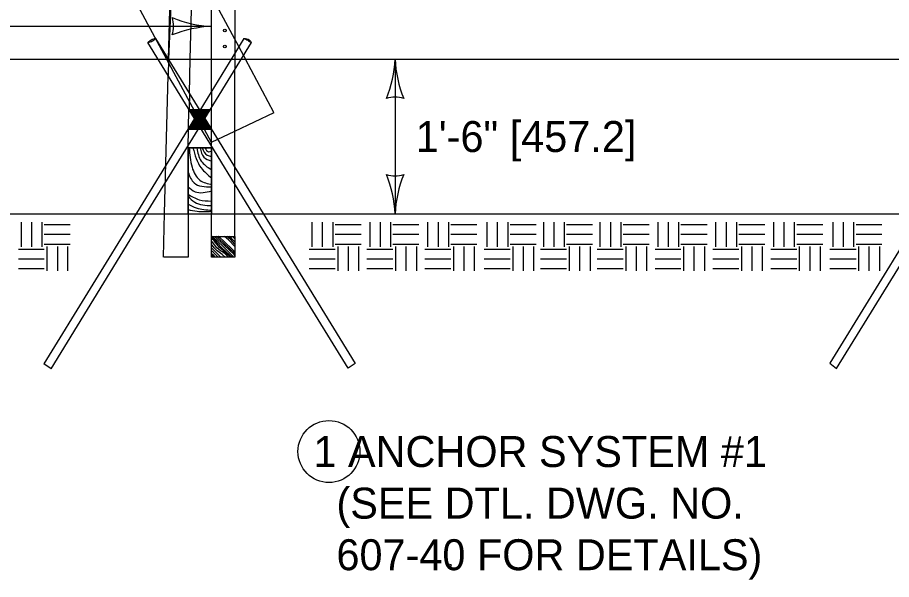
# Model space of a CAD drawing. Extents: x 49991.4 to 50021, y 49987.6 to 50011.4.
# Drawn here: x 50002.489 to 50004.182, y 49993.662 to 49994.752 of the extents above; entities that cross this region are included whole.
import ezdxf

# ---------------------------------------------------------------- set-up
doc = ezdxf.new("R2010")
doc.units = 0
for name, color, linetype in [('Level 1', 7, 'Continuous'), ('Level 2', 7, 'Continuous'), ('Level 3', 7, 'Continuous'), ('Level 4', 7, 'Continuous')]:
    doc.layers.add(name, color=color, linetype=linetype)

msp = doc.modelspace()

# ---------------------------------------------------------------- linework, layer by layer
at = {"layer": 'Level 1'}
for p, q in [((50002.7564, 49994.7111), (50002.842, 49994.5716)), ((50002.9277, 49994.7111), (50002.842, 49994.5716)), ((50002.8321, 49994.5557), (50002.7415, 49994.7031)), ((50002.8518, 49994.5557), (50002.9424, 49994.7031)), ((50000.6947, 49994.6706), (50004.302, 49994.6706)), ((50002.8221, 49994.604), (50002.8238, 49994.6706)), ((50002.865, 49994.6091), (50002.865, 49994.6706)), ((50002.9859, 49994.5674), (50002.9306, 49994.6706)), ((50002.7738, 49994.3725), (50002.7808, 49994.6392)), ((50002.9103, 49994.3725), (50002.9103, 49994.651)), ((50002.8194, 49994.499), (50002.8212, 49994.5733)), ((50002.8214, 49994.5732), (50002.8626, 49994.5732)), ((50002.8226, 49994.5711), (50002.8613, 49994.5711)), ((50002.865, 49994.3725), (50002.865, 49994.5772)), ((50002.8321, 49994.5557), (50002.7194, 49994.3721)), ((50002.824, 49994.5689), (50002.86, 49994.5689)), ((50002.8252, 49994.5668), (50002.8587, 49994.5668)), ((50002.8266, 49994.5648), (50002.8574, 49994.5648)), ((50002.8278, 49994.5626), (50002.8561, 49994.5626)), ((50002.8292, 49994.5605), (50002.8548, 49994.5605)), ((50002.8304, 49994.5584), (50002.8535, 49994.5584)), ((50002.8312, 49994.5541), (50002.8528, 49994.5541)), ((50002.8318, 49994.5562), (50002.8522, 49994.5562)), ((50002.8518, 49994.5558), (50002.9649, 49994.3716)), ((50002.9103, 49994.5314), (50002.9862, 49994.5674)), ((50002.7391, 49994.3721), (50002.842, 49994.5397)), ((50002.8207, 49994.5371), (50002.8632, 49994.5371)), ((50002.8221, 49994.5392), (50002.8619, 49994.5392)), ((50002.8233, 49994.5412), (50002.8606, 49994.5412)), ((50002.8246, 49994.5434), (50002.8592, 49994.5434)), ((50002.826, 49994.5455), (50002.858, 49994.5455)), ((50002.8273, 49994.5477), (50002.8567, 49994.5477)), ((50002.8286, 49994.5498), (50002.8553, 49994.5498)), ((50002.8299, 49994.5519), (50002.854, 49994.5519)), ((50002.9452, 49994.3716), (50002.842, 49994.5397)), ((50002.8194, 49994.5349), (50002.8645, 49994.5349)), ((50002.8646, 49994.499), (50002.8194, 49994.499)), ((50002.8194, 49994.499), (50002.8194, 49994.3713)), ((50002.8194, 49994.499), (50002.8646, 49994.499)), ((50002.8194, 49994.3713), (50002.8194, 49994.499)), ((50002.8646, 49994.3713), (50002.8646, 49994.499)), ((50002.8646, 49994.499), (50002.8646, 49994.3713)), ((50002.865, 49994.3725), (50002.865, 49994.4363)), ((49999.8901, 49994.3711), (50006.2392, 49994.3711)), ((50002.8194, 49994.3713), (50002.8646, 49994.3713)), ((50002.8194, 49994.3713), (50002.8646, 49994.3713)), ((50002.4961, 49994.3547), (50002.4961, 49994.3074)), ((50002.5162, 49994.3547), (50002.5162, 49994.3074)), ((50002.5364, 49994.3547), (50002.5364, 49994.3074)), ((50002.5411, 49994.3503), (50002.5914, 49994.3503)), ((50003.0592, 49994.3547), (50003.0592, 49994.3074)), ((50003.0794, 49994.3547), (50003.0794, 49994.3074)), ((50003.0996, 49994.3547), (50003.0996, 49994.3074)), ((50003.1042, 49994.3503), (50003.1545, 49994.3503)), ((50003.1714, 49994.3547), (50003.1714, 49994.3074)), ((50003.1916, 49994.3547), (50003.1916, 49994.3074)), ((50003.2116, 49994.3547), (50003.2116, 49994.3074)), ((50003.2163, 49994.3503), (50003.2667, 49994.3503)), ((50003.2835, 49994.3547), (50003.2835, 49994.3074)), ((50003.3036, 49994.3547), (50003.3036, 49994.3074)), ((50003.3238, 49994.3547), (50003.3238, 49994.3074)), ((50003.3285, 49994.3503), (50003.3788, 49994.3503)), ((50003.3983, 49994.3547), (50003.3983, 49994.3074)), ((50003.4184, 49994.3547), (50003.4184, 49994.3074)), ((50003.4386, 49994.3547), (50003.4386, 49994.3074)), ((50003.4433, 49994.3503), (50003.4936, 49994.3503)), ((50003.5078, 49994.3547), (50003.5078, 49994.3074)), ((50003.5278, 49994.3547), (50003.5278, 49994.3074)), ((50003.5479, 49994.3547), (50003.5479, 49994.3074)), ((50003.5526, 49994.3503), (50003.603, 49994.3503)), ((50003.6172, 49994.3547), (50003.6172, 49994.3074)), ((50003.6374, 49994.3547), (50003.6374, 49994.3074)), ((50003.6574, 49994.3547), (50003.6574, 49994.3074)), ((50003.6622, 49994.3503), (50003.7125, 49994.3503)), ((50003.7293, 49994.3547), (50003.7293, 49994.3074)), ((50003.7494, 49994.3547), (50003.7494, 49994.3074)), ((50003.7696, 49994.3547), (50003.7696, 49994.3074)), ((50003.7742, 49994.3503), (50003.8246, 49994.3503)), ((50003.8413, 49994.3547), (50003.8413, 49994.3074)), ((50003.8615, 49994.3547), (50003.8615, 49994.3074)), ((50003.8816, 49994.3547), (50003.8816, 49994.3074)), ((50003.8863, 49994.3503), (50003.9366, 49994.3503)), ((50003.9535, 49994.3547), (50003.9535, 49994.3074)), ((50003.9735, 49994.3547), (50003.9735, 49994.3074)), ((50003.9937, 49994.3547), (50003.9937, 49994.3074)), ((50003.9984, 49994.3503), (50004.0488, 49994.3503)), ((50004.0682, 49994.3547), (50004.0682, 49994.3074)), ((50004.0883, 49994.3547), (50004.0883, 49994.3074)), ((50004.1085, 49994.3547), (50004.1085, 49994.3074)), ((50004.1132, 49994.3503), (50004.1635, 49994.3503)), ((50002.5411, 49994.3314), (50002.5914, 49994.3314)), ((50003.1042, 49994.3314), (50003.1545, 49994.3314)), ((50003.2163, 49994.3314), (50003.2667, 49994.3314)), ((50003.3285, 49994.3314), (50003.3788, 49994.3314)), ((50003.4433, 49994.3314), (50003.4936, 49994.3314)), ((50003.5526, 49994.3314), (50003.603, 49994.3314)), ((50003.6622, 49994.3314), (50003.7125, 49994.3314)), ((50003.7742, 49994.3314), (50003.8246, 49994.3314)), ((50003.8863, 49994.3314), (50003.9366, 49994.3314)), ((50003.9984, 49994.3314), (50004.0488, 49994.3314)), ((50004.1132, 49994.3314), (50004.1635, 49994.3314)), ((50002.4908, 49994.3029), (50002.5411, 49994.3029)), ((50002.5411, 49994.3124), (50002.5914, 49994.3124)), ((50002.5461, 49994.3078), (50002.5461, 49994.2604)), ((50002.5663, 49994.3078), (50002.5663, 49994.2604)), ((50002.5863, 49994.3078), (50002.5863, 49994.2604)), ((50003.0539, 49994.3029), (50003.1042, 49994.3029)), ((50003.1042, 49994.3124), (50003.1545, 49994.3124)), ((50003.1093, 49994.3078), (50003.1093, 49994.2604)), ((50003.1294, 49994.3078), (50003.1294, 49994.2604)), ((50003.1496, 49994.3078), (50003.1496, 49994.2604)), ((50003.166, 49994.3029), (50003.2163, 49994.3029)), ((50003.2163, 49994.3124), (50003.2667, 49994.3124)), ((50003.2214, 49994.3078), (50003.2214, 49994.2604)), ((50003.2415, 49994.3078), (50003.2415, 49994.2604)), ((50003.2617, 49994.3078), (50003.2617, 49994.2604)), ((50003.2782, 49994.3029), (50003.3285, 49994.3029)), ((50003.3285, 49994.3124), (50003.3788, 49994.3124)), ((50003.3336, 49994.3078), (50003.3336, 49994.2604)), ((50003.3536, 49994.3078), (50003.3536, 49994.2604)), ((50003.3737, 49994.3078), (50003.3737, 49994.2604)), ((50003.393, 49994.3029), (50003.4433, 49994.3029)), ((50003.4433, 49994.3124), (50003.4936, 49994.3124)), ((50003.4483, 49994.3078), (50003.4483, 49994.2604)), ((50003.4684, 49994.3078), (50003.4684, 49994.2604)), ((50003.4885, 49994.3078), (50003.4885, 49994.2604)), ((50003.5023, 49994.3029), (50003.5526, 49994.3029)), ((50003.5526, 49994.3124), (50003.603, 49994.3124)), ((50003.5577, 49994.3078), (50003.5577, 49994.2604)), ((50003.5778, 49994.3078), (50003.5778, 49994.2604)), ((50003.598, 49994.3078), (50003.598, 49994.2604)), ((50003.6118, 49994.3029), (50003.6622, 49994.3029)), ((50003.6622, 49994.3124), (50003.7125, 49994.3124)), ((50003.6671, 49994.3078), (50003.6671, 49994.2604)), ((50003.6873, 49994.3078), (50003.6873, 49994.2604)), ((50003.7074, 49994.3078), (50003.7074, 49994.2604)), ((50003.7239, 49994.3029), (50003.7742, 49994.3029)), ((50003.7742, 49994.3124), (50003.8246, 49994.3124)), ((50003.7793, 49994.3078), (50003.7793, 49994.2604)), ((50003.7993, 49994.3078), (50003.7993, 49994.2604)), ((50003.8195, 49994.3078), (50003.8195, 49994.2604)), ((50003.836, 49994.3029), (50003.8863, 49994.3029)), ((50003.8863, 49994.3124), (50003.9366, 49994.3124)), ((50003.8914, 49994.3078), (50003.8914, 49994.2604)), ((50003.9115, 49994.3078), (50003.9115, 49994.2604)), ((50003.9317, 49994.3078), (50003.9317, 49994.2604)), ((50003.9481, 49994.3029), (50003.9984, 49994.3029)), ((50003.9984, 49994.3124), (50004.0488, 49994.3124)), ((50004.0034, 49994.3078), (50004.0034, 49994.2604)), ((50004.0236, 49994.3078), (50004.0236, 49994.2604)), ((50004.0437, 49994.3078), (50004.0437, 49994.2604)), ((50004.0628, 49994.3029), (50004.1132, 49994.3029)), ((50004.1132, 49994.3124), (50004.1635, 49994.3124)), ((50004.1182, 49994.3078), (50004.1182, 49994.2604)), ((50004.1382, 49994.3078), (50004.1382, 49994.2604)), ((50004.1584, 49994.3078), (50004.1584, 49994.2604)), ((50002.4908, 49994.2841), (50002.5411, 49994.2841)), ((50003.0539, 49994.2841), (50003.1042, 49994.2841)), ((50003.166, 49994.2841), (50003.2163, 49994.2841)), ((50003.2782, 49994.2841), (50003.3285, 49994.2841)), ((50003.393, 49994.2841), (50003.4433, 49994.2841)), ((50003.5023, 49994.2841), (50003.5526, 49994.2841)), ((50003.6118, 49994.2841), (50003.6622, 49994.2841)), ((50003.7239, 49994.2841), (50003.7742, 49994.2841)), ((50003.836, 49994.2841), (50003.8863, 49994.2841)), ((50003.9481, 49994.2841), (50003.9984, 49994.2841)), ((50004.0628, 49994.2841), (50004.1132, 49994.2841)), ((50002.4908, 49994.2651), (50002.5411, 49994.2651)), ((50003.0539, 49994.2651), (50003.1042, 49994.2651)), ((50003.166, 49994.2651), (50003.2163, 49994.2651)), ((50003.2782, 49994.2651), (50003.3285, 49994.2651)), ((50003.393, 49994.2651), (50003.4433, 49994.2651)), ((50003.5023, 49994.2651), (50003.5526, 49994.2651)), ((50003.6118, 49994.2651), (50003.6622, 49994.2651)), ((50003.7239, 49994.2651), (50003.7742, 49994.2651)), ((50003.836, 49994.2651), (50003.8863, 49994.2651)), ((50003.9481, 49994.2651), (50003.9984, 49994.2651)), ((50004.0628, 49994.2651), (50004.1132, 49994.2651))]:
    msp.add_line(p, q, dxfattribs=at)
for centre in [(50002.8907, 49994.7262), (50002.8907, 49994.6955)]:
    msp.add_ellipse(centre, major_axis=(0.00285, 0), ratio=0.940299, dxfattribs=at)
for points in [[(50002.7415, 49994.7031), (50002.7505, 49994.7062), (50002.7564, 49994.7111)], [(50002.7415, 49994.7031), (50002.75, 49994.7093), (50002.7564, 49994.7111)], [(50002.9277, 49994.7111), (50002.9378, 49994.7084), (50002.9424, 49994.7031)], [(50002.9277, 49994.7111), (50002.935, 49994.7074), (50002.9424, 49994.7031)], [(50002.8219, 49994.499), (50002.8272, 49994.4613), (50002.8424, 49994.4364), (50002.8659, 49994.4277)], [(50002.829, 49994.499), (50002.8448, 49994.4601), (50002.8653, 49994.4404)], [(50002.8363, 49994.4988), (50002.8448, 49994.4734), (50002.8642, 49994.4569)], [(50002.8431, 49994.4987), (50002.8501, 49994.481), (50002.8648, 49994.4734)], [(50002.8466, 49994.4988), (50002.8566, 49994.4849), (50002.8642, 49994.4822)], [(50002.8522, 49994.499), (50002.8589, 49994.4914), (50002.8642, 49994.4926)], [(50002.8195, 49994.4519), (50002.8312, 49994.431), (50002.8648, 49994.4233)], [(50002.8195, 49994.4233), (50002.833, 49994.414), (50002.8653, 49994.4155)], [(50002.8189, 49994.4095), (50002.8407, 49994.3985), (50002.8648, 49994.3958)], [(50002.8195, 49994.4051), (50002.8324, 49994.3936), (50002.8653, 49994.387)], [(50002.8195, 49994.3896), (50002.8354, 49994.3826), (50002.8653, 49994.3782)], [(50002.8195, 49994.3792), (50002.8371, 49994.376), (50002.8642, 49994.376)]]:
    msp.add_spline(points, degree=3, dxfattribs=at)
at = {"layer": 'Level 2'}
msp.add_circle((50003.0924, 49993.9104), 0.06, dxfattribs=at)
msp.add_ellipse((50003.326, 49993.6896), major_axis=(0.00285, 0), ratio=0.940299, dxfattribs=at)
at = {"layer": 'Level 3'}
for p, q in [((50002.2108, 49994.7345), (50002.865, 49994.7345)), ((50003.2204, 49994.6707), (50003.2204, 49994.3711))]:
    msp.add_line(p, q, dxfattribs=at)
for centre, radius, start, end in [((50002.8742, 49994.9566), 0.2223, 247.456, 267.6395), ((50002.7368, 49994.7345), 0.0548, 342.1388, 17.8612), ((50002.8765, 49994.5018), 0.233, 92.8273, 112.0772), ((50002.9983, 49994.6798), 0.2223, 337.456, 357.6395), ((50003.4531, 49994.6822), 0.233, 182.8273, 202.0772), ((50003.2204, 49994.5425), 0.0548, 72.1388, 107.8612), ((50003.2204, 49994.4993), 0.0548, 252.1388, 287.8612), ((50002.9877, 49994.3596), 0.233, 2.8273, 22.0772), ((50003.4426, 49994.3619), 0.2223, 157.456, 177.6395)]:
    msp.add_arc(centre, radius, start, end, dxfattribs=at)
at = {"layer": 'Level 4'}
for p, q in [((50002.7241, 49995.054), (50002.9306, 49994.6706)), ((50002.8238, 49994.6706), (50002.8294, 49994.8804)), ((50002.865, 49994.6706), (50002.865, 49994.8246)), ((50002.8648, 49994.5096), (50002.7094, 49994.7984)), ((50002.7872, 49994.7984), (50002.7817, 49994.6706)), ((50002.7817, 49994.6706), (50002.7851, 49994.7984)), ((50002.9103, 49994.7984), (50002.9103, 49994.651)), ((50002.7817, 49994.6706), (50002.7808, 49994.6392)), ((50002.865, 49994.6091), (50002.865, 49994.5772)), ((50002.8221, 49994.604), (50002.8214, 49994.5732)), ((50002.865, 49994.5098), (50002.9103, 49994.5314)), ((50002.7194, 49994.3721), (50002.5401, 49994.0801)), ((50002.5541, 49994.0708), (50002.7391, 49994.3721)), ((50002.7716, 49994.2873), (50002.7738, 49994.3725)), ((50002.8197, 49994.3713), (50002.8197, 49994.2873)), ((50002.865, 49994.2873), (50002.865, 49994.3725)), ((50002.9103, 49994.3272), (50002.9103, 49994.3725)), ((50003.1293, 49994.0717), (50002.9452, 49994.3716)), ((50002.9649, 49994.3716), (50003.1432, 49994.0808)), ((50004.2402, 49994.3712), (50004.0624, 49994.0816)), ((50004.0757, 49994.0715), (50004.2598, 49994.3712)), ((50002.8197, 49994.2873), (50002.7723, 49994.2873)), ((50002.5541, 49994.0708), (50002.5401, 49994.0801)), ((50003.1432, 49994.0808), (50003.1293, 49994.0717)), ((50004.0624, 49994.0816), (50004.0757, 49994.0715))]:
    msp.add_line(p, q, dxfattribs=at)
for points in [[(50002.865, 49994.3272), (50002.9103, 49994.3272), (50002.9103, 49994.2873)], [(50002.9047, 49994.2873), (50002.8939, 49994.297), (50002.8838, 49994.3067), (50002.8711, 49994.32), (50002.865, 49994.3253)], [(50002.902, 49994.2873), (50002.8926, 49994.2958), (50002.8802, 49994.3059), (50002.8698, 49994.3188), (50002.865, 49994.323)], [(50002.8977, 49994.2873), (50002.8912, 49994.2936), (50002.886, 49994.2972), (50002.8821, 49994.2993), (50002.8754, 49994.3055), (50002.8671, 49994.3162), (50002.865, 49994.318)], [(50002.9081, 49994.2873), (50002.9039, 49994.2914), (50002.8897, 49994.3058), (50002.8761, 49994.3187), (50002.8685, 49994.3249), (50002.8657, 49994.3272)], [(50002.9103, 49994.2905), (50002.9086, 49994.292), (50002.8901, 49994.3097), (50002.8708, 49994.3272)], [(50002.9103, 49994.294), (50002.8793, 49994.3235), (50002.8748, 49994.3272)], [(50002.9103, 49994.2974), (50002.9034, 49994.3037), (50002.8912, 49994.3157), (50002.8788, 49994.3271), (50002.8786, 49994.3272)], [(50002.9103, 49994.3075), (50002.8975, 49994.321), (50002.8899, 49994.3272)], [(50002.9103, 49994.3118), (50002.9094, 49994.3127), (50002.9022, 49994.3211), (50002.8945, 49994.3272)], [(50002.9103, 49994.3167), (50002.9039, 49994.3231), (50002.8986, 49994.3272)], [(50002.9103, 49994.3226), (50002.9055, 49994.3272)], [(50002.8913, 49994.2873), (50002.8856, 49994.2923), (50002.8801, 49994.2963), (50002.8757, 49994.2993), (50002.8701, 49994.3049), (50002.8663, 49994.3101), (50002.865, 49994.3114)], [(50002.883, 49994.2873), (50002.8698, 49994.2998), (50002.865, 49994.3052)], [(50002.878, 49994.2873), (50002.8684, 49994.2971), (50002.865, 49994.2996)], [(50002.8723, 49994.2873), (50002.8692, 49994.2905), (50002.865, 49994.2937)], [(50002.8685, 49994.2873), (50002.8674, 49994.2885), (50002.865, 49994.2905)], [(50002.9103, 49994.2873), (50002.865, 49994.2873)]]:
    msp.add_lwpolyline(points, dxfattribs=at)

# ---------------------------------------------------------------- texts
at = {"layer": 'Level 2'}
for s, p in [('1\'-6" [457.2]', (50003.2604, 49994.4909)), ('1 ANCHOR SYSTEM #1', (50003.0623, 49993.8804)), ('  (SEE DTL. DWG. NO. ', (50003.0623, 49993.7804)), ('  607-40 FOR DETAILS)', (50003.0623, 49993.6804))]:
    msp.add_text(s, height=0.06, dxfattribs=at).set_placement(p)

doc.saveas('drawing.dxf')
